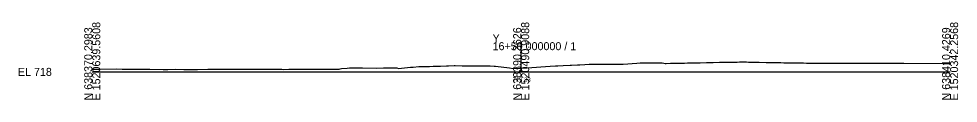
# Model space of a CAD drawing. Extents: x -26 to 303, y -10 to 5039.
# Drawn here: x -25.7 to 302.8, y -9.7 to 17.3 of the extents above; entities that cross this region are included whole.
import ezdxf

# ---------------------------------------------------------------- set-up
doc = ezdxf.new("R2010")
doc.units = 0
for name, color, linetype in [('Default', 7, 'Continuous'), ('Exist Cross Section Cell', 7, 'Continuous'), ('Exist XS Center Line Elevation Label', 7, 'Continuous'), ('Exist XS Ground Line', 7, 'Continuous')]:
    doc.layers.add(name, color=color, linetype=linetype)

msp = doc.modelspace()

# ---------------------------------------------------------------- linework, layer by layer
at = {"layer": 'Exist Cross Section Cell'}
for p, q in [((150, 0), (150, 10.4)), ((0, 0), (150, 0)), ((150, 0), (300, 0))]:
    msp.add_line(p, q, dxfattribs=at)
at = {"layer": 'Exist XS Ground Line'}
msp.add_lwpolyline([(0, 1.01), (2.41, 0.95), (8.47, 1.02), (10.44, 0.99), (11.92, 0.97), (17.96, 0.93), (18.99, 0.93), (20.19, 0.94), (24.79, 0.88), (26.45, 0.89), (29.21, 0.9), (32.01, 0.79), (36.82, 0.86), (40.38, 0.93), (41.3, 0.93), (41.97, 0.93), (43.76, 0.92), (46.07, 0.91), (46.61, 0.91), (48.6, 0.92), (50.1, 0.92), (51.12, 0.92), (52.32, 0.92), (53.64, 0.92), (55.37, 0.93), (56.16, 0.93), (56.77, 0.93), (58.69, 0.93), (61.24, 0.93), (63.73, 0.91), (64.13, 0.91), (66.25, 0.9), (67.05, 0.89), (68.77, 0.91), (69.97, 0.92), (71.29, 0.93), (72.89, 0.94), (73.81, 0.95), (75.81, 0.95), (76.33, 0.96), (78.86, 0.98), (79.66, 0.98), (81.66, 0.98), (83.81, 0.98), (84.26, 0.98), (85.67, 0.98), (86.3, 0.98), (86.73, 1.09), (87.17, 1.19), (89.15, 1.32), (90, 1.38), (90.92, 1.45), (94.5, 1.41), (99.52, 1.36), (101.86, 1.38), (106.49, 1.41), (107.09, 1.21), (108.1, 1.29), (109.14, 1.38), (111.3, 1.63), (111.68, 1.67), (112.19, 1.7), (114.23, 1.84), (114.66, 1.88), (115, 1.89), (116.73, 1.9), (117.97, 1.93), (119.26, 1.97), (120.93, 2.02), (121.77, 2.04), (123.84, 2.1), (124.28, 2.12), (124.62, 2.13), (126.51, 2.19), (126.88, 2.2), (129.32, 2.17), (131.28, 2.18), (131.84, 2.18), (132.57, 2.17), (134.37, 2.16), (135.52, 2.15), (136.91, 2.13), (137.68, 2.13), (138.77, 2.13), (139.14, 2.11), (140.52, 2.04), (141.05, 2.02), (145.89, 1.39), (147.17, 1.21), (150, 1.33), (152.15, 1.43), (160.12, 1.98), (162.02, 2.13), (162.84, 2.17), (164.69, 2.24), (167.19, 2.35), (167.59, 2.37), (169.71, 2.47), (170.51, 2.5), (172.23, 2.58), (173.83, 2.67), (174.73, 2.67), (175.75, 2.68), (177.24, 2.7), (179.22, 2.72), (179.77, 2.72), (182.28, 2.74), (183.11, 2.75), (184.69, 2.76), (185.28, 2.76), (185.69, 2.76), (190.48, 3.06), (191.63, 3.14), (192.76, 3.15), (193.61, 3.16), (196.5, 3.19), (198.11, 3.2), (199.35, 3.21), (199.92, 3.08), (200.36, 2.99), (200.7, 2.98), (202.19, 3), (203.74, 3.03), (204.56, 3.04), (205.96, 3.07), (207.07, 3.1), (208.19, 3.12), (209.6, 3.15), (210.42, 3.17), (212.11, 3.2), (212.63, 3.21), (214.86, 3.25), (216.53, 3.29), (217.16, 3.3), (219.3, 3.35), (219.68, 3.36), (221.53, 3.39), (222.21, 3.4), (222.79, 3.42), (223.93, 3.43), (225.52, 3.46), (226.39, 3.47), (227.55, 3.47), (228.52, 3.47), (228.85, 3.47), (229.48, 3.46), (231.61, 3.39), (233.26, 3.36), (235.63, 3.3), (237.23, 3.27), (239.22, 3.26), (240.81, 3.25), (241.89, 3.23), (248.69, 3.13), (249.82, 3.11), (250.75, 3.1), (251.78, 3.08), (261.39, 3.03), (262.2, 3.02), (263.09, 3.02), (272.43, 3.08), (273.44, 3.08), (274.46, 3.07), (283.33, 3.04), (283.82, 3.04), (297.57, 2.98), (298.1, 2.97), (298.53, 2.97), (300, 2.95)], dxfattribs=at)

# ---------------------------------------------------------------- texts
at = {"layer": 'Default'}
msp.add_text('-', height=0.0001, dxfattribs=at).set_placement((0, 0))
at = {"layer": 'Exist Cross Section Cell'}
for s, p in [('E 1520639.5608', (2.8, -10)), ('E 1520490.9088', (152.8, -10)), ('E 1520342.2568', (302.8, -10)), ('N 638370.2983', (0, -10)), ('N 638390.3626', (150, -10)), ('N 638410.4269', (300, -10))]:
    msp.add_text(s, height=2.8, rotation=90, dxfattribs=at).set_placement(p)
for s, p in [('Y', (140, 10.4)), ('16+50.000000 / 1', (140, 7.6)), ('EL 718', (-26, -1.4))]:
    msp.add_text(s, height=2.8, dxfattribs=at).set_placement(p)
at = {"layer": 'Exist XS Center Line Elevation Label'}
msp.add_text('719.33', height=1.5, dxfattribs=at).set_placement((146.99, -3.42))

doc.saveas('drawing.dxf')
